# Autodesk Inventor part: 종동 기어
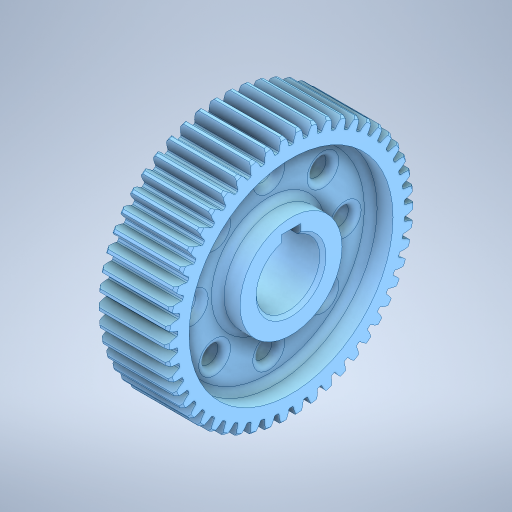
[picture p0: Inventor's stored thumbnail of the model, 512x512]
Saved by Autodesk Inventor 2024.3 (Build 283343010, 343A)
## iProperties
Created: 2025-11
Part Number: 종동 기어
Material: 강철, 탄소
Document SubType Name: Modeling
Designer: PC2-15
Density: 7.85 g/cm^3
Appearance: 기본값
Author: jhkim
Sending System: Autodesk Inventor 2026
Preprocessor: ST-DEVELOPER v20.1
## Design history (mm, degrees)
node "종동 기어1"
node "솔리드2"
node "솔리드1"
